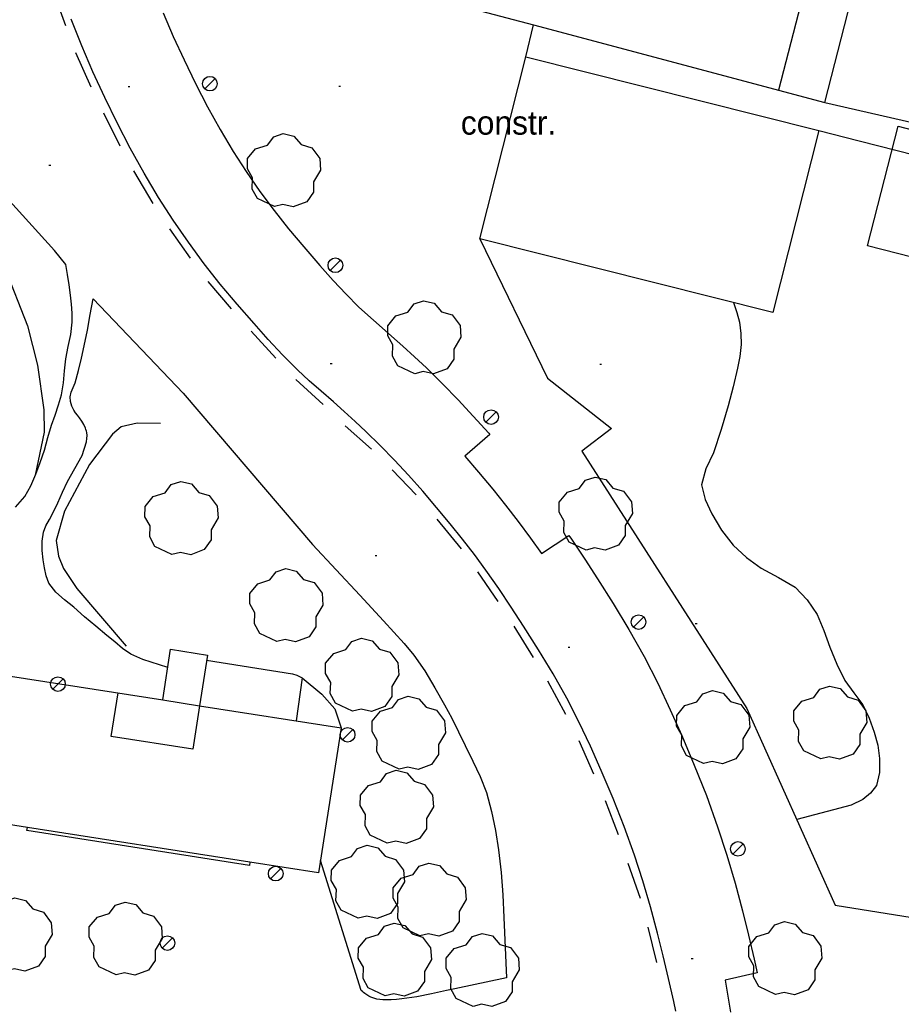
# Model space of a CAD drawing. Extents: x 431390 to 432653, y 4586754 to 4589600.
# Drawn here: x 431476.3 to 431524.5, y 4587127.2 to 4587181.2 of the extents above; entities that cross this region are included whole.
import ezdxf

# ---------------------------------------------------------------- set-up
doc = ezdxf.new("R2010")
doc.units = 0
for name, color, linetype in [('COM_06_LN', 7, 'Continuous'), ('COM_16_LN', 7, 'Continuous'), ('COM_17LS_LN', 7, 'Continuous'), ('CON_01_LN', 7, 'Continuous'), ('CON_01FI_LN', 7, 'Continuous'), ('CON_04_LN', 7, 'Continuous'), ('CON_06_LN', 7, 'Continuous'), ('CON_07_LN', 7, 'Continuous'), ('CON_15_LN', 7, 'Continuous'), ('CON_16_LN', 7, 'Continuous'), ('CON_19_LN', 7, 'Continuous'), ('ENE_06_PT', 7, 'Continuous'), ('ORO_03_PT', 7, 'Continuous'), ('TOP_13CN_TX', 7, 'Continuous'), ('VEG_03_PT', 7, 'Continuous'), ('VEG_04_LN', 7, 'Continuous'), ('VEG_07LS_LN', 7, 'Continuous')]:
    doc.layers.add(name, color=color, linetype=linetype)

msp = doc.modelspace()

# ---------------------------------------------------------------- linework, layer by layer
at = {"layer": 'COM_06_LN'}
msp.add_lwpolyline([(431515.31, 4587165.747), (431515.484, 4587165.212), (431515.63, 4587164.67), (431515.714, 4587164.062), (431515.73, 4587163.45), (431515.655, 4587162.808), (431515.53, 4587162.17), (431515.291, 4587161.135), (431515.01, 4587160.11), (431514.63, 4587158.819), (431514.21, 4587157.54), (431513.805, 4587156.659), (431513.56, 4587155.78), (431513.756, 4587154.98), (431514.13, 4587154.2), (431514.651, 4587153.304), (431515.29, 4587152.49), (431516.017, 4587151.813), (431516.82, 4587151.22), (431517.77, 4587150.725), (431518.68, 4587150.19), (431519.339, 4587149.497), (431519.88, 4587148.7), (431520.256, 4587147.821), (431520.58, 4587146.91), (431520.959, 4587145.978), (431521.4, 4587145.08), (431521.894, 4587144.417), (431522.38, 4587143.75), (431522.73, 4587143.028), (431523, 4587142.27), (431523.191, 4587141.551), (431523.29, 4587140.82), (431523.296, 4587140.057), (431523.12, 4587139.35), (431522.792, 4587138.928), (431522.37, 4587138.58), (431521.745, 4587138.272), (431518.764, 4587137.478)], dxfattribs=at)
at = {"layer": 'COM_16_LN'}
for points in [[(431478.81, 4587180.89), (431478.14, 4587182.76)], [(431480.2, 4587177.52), (431479.37, 4587179.41)], [(431481.79, 4587174.31), (431480.9, 4587176.11)], [(431483.59, 4587171.16), (431482.53, 4587172.96)], [(431485.63, 4587168.17), (431484.5, 4587169.78)], [(431487.87, 4587165.4), (431486.6, 4587166.9)], [(431490.29, 4587162.71), (431488.94, 4587164.18)], [(431492.89, 4587160.17), (431491.38, 4587161.55)], [(431495.52, 4587157.73), (431494.09, 4587159.01)], [(431497.96, 4587155.23), (431496.66, 4587156.61)], [(431500.44, 4587152.29), (431499.12, 4587153.91)], [(431502.44, 4587149.4), (431501.34, 4587151.03)], [(431504.38, 4587146.35), (431503.33, 4587148.06)], [(431506.15, 4587143.22), (431505.17, 4587145.05)], [(431507.68, 4587139.97), (431506.88, 4587141.78)], [(431509.02, 4587136.64), (431508.31, 4587138.51)], [(431510.22, 4587133.16), (431509.55, 4587135.09)], [(431511.12, 4587129.67), (431510.65, 4587131.6)]]:
    msp.add_lwpolyline(points, dxfattribs=at)
at = {"layer": 'COM_17LS_LN'}
for points in [[(431484.133, 4587181.599), (431484.685, 4587180.303), (431485.276, 4587179.015), (431485.905, 4587177.735), (431486.568, 4587176.459), (431487.255, 4587175.219), (431487.971, 4587174.018), (431488.679, 4587172.917), (431489.425, 4587171.832), (431490.199, 4587170.78), (431490.981, 4587169.789), (431491.817, 4587168.795), (431492.707, 4587167.779), (431493.435, 4587166.963), (431494.134, 4587166.204), (431494.804, 4587165.525), (431495.317, 4587165.054), (431495.936, 4587164.515), (431496.621, 4587163.915), (431497.242, 4587163.359), (431497.872, 4587162.791), (431498.532, 4587162.175), (431499.413, 4587161.307), (431500.261, 4587160.431), (431501.083, 4587159.548), (431501.929, 4587158.606), (431501.993, 4587158.531), (431500.633, 4587157.351), (431501.377, 4587156.486), (431502.157, 4587155.543), (431502.854, 4587154.674), (431503.54, 4587153.786), (431504.215, 4587152.873), (431504.81, 4587152.022), (431506.307, 4587153.022), (431506.448, 4587152.821), (431507.18, 4587151.723), (431507.874, 4587150.645), (431508.729, 4587149.297), (431509.591, 4587147.88), (431510.43, 4587146.391), (431511.175, 4587144.932), (431511.851, 4587143.492), (431512.482, 4587142.073), (431513.168, 4587140.459), (431513.827, 4587138.797), (431514.442, 4587137.093), (431514.945, 4587135.538), (431515.393, 4587134.003), (431515.804, 4587132.486), (431516.137, 4587131.169), (431516.445, 4587129.853), (431516.61, 4587129.105), (431514.854, 4587128.71), (431514.998, 4587127.831), (431515.143, 4587126.952)], [(431512.166, 4587127.005), (431512.04, 4587127.54), (431511.765, 4587128.788), (431511.473, 4587130.032), (431511.16, 4587131.27), (431510.772, 4587132.703), (431510.356, 4587134.128), (431509.9, 4587135.54), (431509.338, 4587137.096), (431508.727, 4587138.636), (431508.08, 4587140.16), (431507.486, 4587141.496), (431506.864, 4587142.819), (431506.2, 4587144.12), (431505.448, 4587145.454), (431504.651, 4587146.765), (431503.83, 4587148.06), (431503.165, 4587149.092), (431502.484, 4587150.114), (431501.78, 4587151.12), (431501.147, 4587151.976), (431500.495, 4587152.819), (431499.83, 4587153.65), (431499.084, 4587154.551), (431498.321, 4587155.439), (431497.54, 4587156.31), (431496.78, 4587157.126), (431496.004, 4587157.928), (431495.21, 4587158.71), (431494.627, 4587159.254), (431494.035, 4587159.788), (431493.44, 4587160.32), (431492.779, 4587160.899), (431492.116, 4587161.476), (431491.47, 4587162.07), (431490.66, 4587162.89), (431489.878, 4587163.739), (431489.11, 4587164.6), (431488.174, 4587165.669), (431487.26, 4587166.756), (431486.38, 4587167.87), (431485.513, 4587169.05), (431484.682, 4587170.258), (431483.89, 4587171.49), (431483.093, 4587172.826), (431482.338, 4587174.189), (431481.62, 4587175.57), (431480.94, 4587176.956), (431480.295, 4587178.36), (431479.69, 4587179.78), (431479.111, 4587181.254)], [(431525.92, 4587168.011), (431522.638, 4587168.852), (431524.313, 4587175.389), (431527.598, 4587174.547)]]:
    msp.add_lwpolyline(points, dxfattribs=at)
at = {"layer": 'CON_01_LN'}
msp.add_lwpolyline([(431493.124, 4587188.755), (431493.14, 4587188.711), (431493.706, 4587187.505), (431495.71, 4587183.235), (431504.385, 4587180.928)], dxfattribs=at)
at = {"layer": 'CON_01FI_LN'}
for points in [[(431520.299, 4587176.697), (431523, 4587187.223), (431523.952, 4587190.935), (431501.15, 4587196.755), (431498.849, 4587187.456), (431498.747, 4587187.043), (431498.539, 4587187.09), (431497.301, 4587187.471), (431493.124, 4587188.755)], [(431504.385, 4587180.928), (431520.299, 4587176.697)], [(431484.113, 4587144.024), (431484.545, 4587146.793), (431486.557, 4587146.479), (431486.124, 4587143.71), (431493.872, 4587142.5), (431492.633, 4587134.571), (431488.881, 4587135.157)], [(431476.715, 4587137.058), (431472.661, 4587137.691), (431473.9, 4587145.62), (431484.113, 4587144.024)], [(431488.881, 4587135.157), (431488.853, 4587134.978), (431476.687, 4587136.878), (431476.715, 4587137.058)]]:
    msp.add_lwpolyline(points, dxfattribs=at)
at = {"layer": 'CON_04_LN'}
for points in [[(431521.425, 4587191.58), (431520.314, 4587187.249), (431517.778, 4587177.367)], [(431484.113, 4587144.024), (431486.124, 4587143.71), (431485.753, 4587141.335), (431481.297, 4587142.031), (431481.668, 4587144.406)], [(431488.881, 4587135.157), (431476.715, 4587137.058)]]:
    msp.add_lwpolyline(points, dxfattribs=at)
at = {"layer": 'CON_06_LN'}
msp.add_lwpolyline([(431503.957, 4587179.188), (431519.965, 4587175.151), (431517.457, 4587165.206), (431501.449, 4587169.243), (431503.957, 4587179.188)], dxfattribs=at)
at = {"layer": 'CON_07_LN'}
msp.add_lwpolyline([(431486.512, 4587146.191), (431491.21, 4587145.46), (431491.44, 4587145.37), (431491.73, 4587145.24), (431491.402, 4587142.886)], dxfattribs=at)
at = {"layer": 'CON_15_LN'}
msp.add_lwpolyline([(431501.449, 4587169.243), (431505.138, 4587161.618), (431508.644, 4587158.874), (431507.022, 4587157.621), (431516.036, 4587143.553), (431520.864, 4587132.801), (431526.443, 4587131.905), (431525.002, 4587127.695)], dxfattribs=at)
at = {"layer": 'CON_16_LN'}
for points in [[(431519.965, 4587175.151), (431522.185, 4587174.591)], [(431491.73, 4587145.24), (431492.8, 4587144.34), (431493.52, 4587143.53), (431493.872, 4587142.5)]]:
    msp.add_lwpolyline(points, dxfattribs=at)
at = {"layer": 'CON_19_LN'}
for points in [[(431503.957, 4587179.188), (431504.385, 4587180.928)], [(431520.299, 4587176.697), (431527.717, 4587175.001)], [(431522.185, 4587174.591), (431527.269, 4587173.3)]]:
    msp.add_lwpolyline(points, dxfattribs=at)
at = {"layer": 'ENE_06_PT'}
for p, q in [((431486.972, 4587178.002), (431486.406, 4587177.436)), ((431493.832, 4587168.072), (431493.266, 4587167.506)), ((431502.342, 4587159.772), (431501.776, 4587159.206)), ((431510.402, 4587148.562), (431509.836, 4587147.996)), ((431478.667, 4587145.173), (431478.101, 4587144.607)), ((431494.502, 4587142.402), (431493.936, 4587141.836)), ((431515.832, 4587136.162), (431515.266, 4587135.596)), ((431490.572, 4587134.812), (431490.006, 4587134.246)), ((431484.652, 4587131.012), (431484.086, 4587130.446))]:
    msp.add_line(p, q, dxfattribs=at)
for centre in [(431486.689, 4587177.719), (431493.549, 4587167.789), (431502.059, 4587159.489), (431510.119, 4587148.279), (431478.384, 4587144.89), (431494.219, 4587142.119), (431515.549, 4587135.879), (431490.289, 4587134.529), (431484.369, 4587130.729)]:
    msp.add_circle(centre, 0.4, dxfattribs=at)
at = {"layer": 'ORO_03_PT'}
for p, q in [((431482.22, 4587177.56), (431482.32, 4587177.56)), ((431493.73, 4587177.58), (431493.83, 4587177.58)), ((431477.89, 4587173.27), (431477.99, 4587173.27)), ((431493.271, 4587162.416), (431493.371, 4587162.416)), ((431508, 4587162.38), (431508.1, 4587162.38)), ((431495.72, 4587151.93), (431495.82, 4587151.93)), ((431513.22, 4587148.21), (431513.32, 4587148.21)), ((431506.266, 4587146.913), (431506.366, 4587146.913)), ((431513, 4587129.878), (431513.1, 4587129.878))]:
    msp.add_line(p, q, dxfattribs=at)
at = {"layer": 'VEG_03_PT'}
for points in [[(431490.214, 4587171.001), (431489.287, 4587171.436), (431488.999, 4587171.957), (431489.022, 4587172.571), (431488.74, 4587173.063), (431488.748, 4587173.626), (431489.189, 4587174.161), (431489.842, 4587174.365), (431490.177, 4587174.816), (431490.703, 4587174.986), (431491.283, 4587174.853), (431491.683, 4587174.387), (431492.257, 4587174.217), (431492.691, 4587173.634), (431492.74, 4587172.992), (431492.357, 4587172.345), (431492.357, 4587171.795), (431491.985, 4587171.261), (431491.246, 4587170.986), (431490.681, 4587171.114), (431490.214, 4587171.001)], [(431497.884, 4587161.861), (431496.957, 4587162.296), (431496.669, 4587162.817), (431496.692, 4587163.431), (431496.41, 4587163.923), (431496.418, 4587164.486), (431496.859, 4587165.021), (431497.512, 4587165.225), (431497.847, 4587165.676), (431498.373, 4587165.846), (431498.953, 4587165.713), (431499.353, 4587165.247), (431499.927, 4587165.077), (431500.361, 4587164.494), (431500.41, 4587163.852), (431500.027, 4587163.205), (431500.027, 4587162.655), (431499.655, 4587162.121), (431498.916, 4587161.846), (431498.351, 4587161.974), (431497.884, 4587161.861)], [(431507.254, 4587152.221), (431506.327, 4587152.656), (431506.039, 4587153.177), (431506.062, 4587153.791), (431505.78, 4587154.283), (431505.788, 4587154.846), (431506.229, 4587155.381), (431506.882, 4587155.585), (431507.217, 4587156.036), (431507.743, 4587156.206), (431508.323, 4587156.073), (431508.723, 4587155.607), (431509.297, 4587155.437), (431509.731, 4587154.854), (431509.78, 4587154.212), (431509.397, 4587153.565), (431509.397, 4587153.015), (431509.025, 4587152.481), (431508.286, 4587152.206), (431507.721, 4587152.334), (431507.254, 4587152.221)], [(431484.614, 4587151.981), (431483.687, 4587152.416), (431483.399, 4587152.937), (431483.422, 4587153.551), (431483.14, 4587154.043), (431483.148, 4587154.606), (431483.589, 4587155.141), (431484.242, 4587155.345), (431484.577, 4587155.796), (431485.103, 4587155.966), (431485.683, 4587155.833), (431486.083, 4587155.367), (431486.657, 4587155.197), (431487.091, 4587154.614), (431487.14, 4587153.972), (431486.757, 4587153.325), (431486.757, 4587152.775), (431486.385, 4587152.241), (431485.646, 4587151.966), (431485.081, 4587152.094), (431484.614, 4587151.981)], [(431490.344, 4587147.221), (431489.417, 4587147.656), (431489.129, 4587148.177), (431489.152, 4587148.791), (431488.87, 4587149.283), (431488.878, 4587149.846), (431489.319, 4587150.381), (431489.972, 4587150.585), (431490.307, 4587151.036), (431490.833, 4587151.206), (431491.413, 4587151.073), (431491.813, 4587150.607), (431492.387, 4587150.437), (431492.821, 4587149.854), (431492.87, 4587149.212), (431492.487, 4587148.565), (431492.487, 4587148.015), (431492.115, 4587147.481), (431491.376, 4587147.206), (431490.811, 4587147.334), (431490.344, 4587147.221)], [(431494.484, 4587143.411), (431493.557, 4587143.846), (431493.269, 4587144.367), (431493.292, 4587144.981), (431493.01, 4587145.473), (431493.018, 4587146.036), (431493.459, 4587146.571), (431494.112, 4587146.775), (431494.447, 4587147.226), (431494.973, 4587147.396), (431495.553, 4587147.263), (431495.953, 4587146.797), (431496.527, 4587146.627), (431496.961, 4587146.044), (431497.01, 4587145.402), (431496.627, 4587144.755), (431496.627, 4587144.205), (431496.255, 4587143.671), (431495.516, 4587143.396), (431494.951, 4587143.524), (431494.484, 4587143.411)], [(431513.674, 4587140.551), (431512.747, 4587140.986), (431512.459, 4587141.507), (431512.482, 4587142.121), (431512.2, 4587142.613), (431512.208, 4587143.176), (431512.649, 4587143.711), (431513.302, 4587143.915), (431513.637, 4587144.366), (431514.163, 4587144.536), (431514.743, 4587144.403), (431515.143, 4587143.937), (431515.717, 4587143.767), (431516.151, 4587143.184), (431516.2, 4587142.542), (431515.817, 4587141.895), (431515.817, 4587141.345), (431515.445, 4587140.811), (431514.706, 4587140.536), (431514.141, 4587140.664), (431513.674, 4587140.551)], [(431520.074, 4587140.801), (431519.147, 4587141.236), (431518.859, 4587141.757), (431518.882, 4587142.371), (431518.6, 4587142.863), (431518.608, 4587143.426), (431519.049, 4587143.961), (431519.702, 4587144.165), (431520.037, 4587144.616), (431520.563, 4587144.786), (431521.143, 4587144.653), (431521.543, 4587144.187), (431522.117, 4587144.017), (431522.551, 4587143.434), (431522.6, 4587142.792), (431522.217, 4587142.145), (431522.217, 4587141.595), (431521.845, 4587141.061), (431521.106, 4587140.786), (431520.541, 4587140.914), (431520.074, 4587140.801)], [(431497.034, 4587140.241), (431496.107, 4587140.676), (431495.819, 4587141.197), (431495.842, 4587141.811), (431495.56, 4587142.303), (431495.568, 4587142.866), (431496.009, 4587143.401), (431496.662, 4587143.605), (431496.997, 4587144.056), (431497.523, 4587144.226), (431498.103, 4587144.093), (431498.503, 4587143.627), (431499.077, 4587143.457), (431499.511, 4587142.874), (431499.56, 4587142.232), (431499.177, 4587141.585), (431499.177, 4587141.035), (431498.805, 4587140.501), (431498.066, 4587140.226), (431497.501, 4587140.354), (431497.034, 4587140.241)], [(431496.384, 4587136.191), (431495.457, 4587136.626), (431495.169, 4587137.147), (431495.192, 4587137.761), (431494.91, 4587138.253), (431494.918, 4587138.816), (431495.359, 4587139.351), (431496.012, 4587139.555), (431496.347, 4587140.006), (431496.873, 4587140.176), (431497.453, 4587140.043), (431497.853, 4587139.577), (431498.427, 4587139.407), (431498.861, 4587138.824), (431498.91, 4587138.182), (431498.527, 4587137.535), (431498.527, 4587136.985), (431498.155, 4587136.451), (431497.416, 4587136.176), (431496.851, 4587136.304), (431496.384, 4587136.191)], [(431494.794, 4587132.091), (431493.867, 4587132.526), (431493.579, 4587133.047), (431493.602, 4587133.661), (431493.32, 4587134.153), (431493.328, 4587134.716), (431493.769, 4587135.251), (431494.422, 4587135.455), (431494.757, 4587135.906), (431495.283, 4587136.076), (431495.863, 4587135.943), (431496.263, 4587135.477), (431496.837, 4587135.307), (431497.271, 4587134.724), (431497.32, 4587134.082), (431496.937, 4587133.435), (431496.937, 4587132.885), (431496.565, 4587132.351), (431495.826, 4587132.076), (431495.261, 4587132.204), (431494.794, 4587132.091)], [(431498.174, 4587131.121), (431497.247, 4587131.556), (431496.959, 4587132.077), (431496.982, 4587132.691), (431496.7, 4587133.183), (431496.708, 4587133.746), (431497.149, 4587134.281), (431497.802, 4587134.485), (431498.137, 4587134.936), (431498.663, 4587135.106), (431499.243, 4587134.973), (431499.643, 4587134.507), (431500.217, 4587134.337), (431500.651, 4587133.754), (431500.7, 4587133.112), (431500.317, 4587132.465), (431500.317, 4587131.915), (431499.945, 4587131.381), (431499.206, 4587131.106), (431498.641, 4587131.234), (431498.174, 4587131.121)], [(431475.544, 4587129.211), (431474.617, 4587129.646), (431474.329, 4587130.167), (431474.352, 4587130.781), (431474.07, 4587131.273), (431474.078, 4587131.836), (431474.519, 4587132.371), (431475.172, 4587132.575), (431475.507, 4587133.026), (431476.033, 4587133.196), (431476.613, 4587133.063), (431477.013, 4587132.597), (431477.587, 4587132.427), (431478.021, 4587131.844), (431478.07, 4587131.202), (431477.687, 4587130.555), (431477.687, 4587130.005), (431477.315, 4587129.471), (431476.576, 4587129.196), (431476.011, 4587129.324), (431475.544, 4587129.211)], [(431481.564, 4587128.991), (431480.637, 4587129.426), (431480.349, 4587129.947), (431480.372, 4587130.561), (431480.09, 4587131.053), (431480.098, 4587131.616), (431480.539, 4587132.151), (431481.192, 4587132.355), (431481.527, 4587132.806), (431482.053, 4587132.976), (431482.633, 4587132.843), (431483.033, 4587132.377), (431483.607, 4587132.207), (431484.041, 4587131.624), (431484.09, 4587130.982), (431483.707, 4587130.335), (431483.707, 4587129.785), (431483.335, 4587129.251), (431482.596, 4587128.976), (431482.031, 4587129.104), (431481.564, 4587128.991)], [(431517.614, 4587127.921), (431516.687, 4587128.356), (431516.399, 4587128.877), (431516.422, 4587129.491), (431516.14, 4587129.983), (431516.148, 4587130.546), (431516.589, 4587131.081), (431517.242, 4587131.285), (431517.577, 4587131.736), (431518.103, 4587131.906), (431518.683, 4587131.773), (431519.083, 4587131.307), (431519.657, 4587131.137), (431520.091, 4587130.554), (431520.14, 4587129.912), (431519.757, 4587129.265), (431519.757, 4587128.715), (431519.385, 4587128.181), (431518.646, 4587127.906), (431518.081, 4587128.034), (431517.614, 4587127.921)], [(431496.274, 4587127.841), (431495.347, 4587128.276), (431495.059, 4587128.797), (431495.082, 4587129.411), (431494.8, 4587129.903), (431494.808, 4587130.466), (431495.249, 4587131.001), (431495.902, 4587131.205), (431496.237, 4587131.656), (431496.763, 4587131.826), (431497.343, 4587131.693), (431497.743, 4587131.227), (431498.317, 4587131.057), (431498.751, 4587130.474), (431498.8, 4587129.832), (431498.417, 4587129.185), (431498.417, 4587128.635), (431498.045, 4587128.101), (431497.306, 4587127.826), (431496.741, 4587127.954), (431496.274, 4587127.841)], [(431501.074, 4587127.271), (431500.147, 4587127.706), (431499.859, 4587128.227), (431499.882, 4587128.841), (431499.6, 4587129.333), (431499.608, 4587129.896), (431500.049, 4587130.431), (431500.702, 4587130.635), (431501.037, 4587131.086), (431501.563, 4587131.256), (431502.143, 4587131.123), (431502.543, 4587130.657), (431503.117, 4587130.487), (431503.551, 4587129.904), (431503.6, 4587129.262), (431503.217, 4587128.615), (431503.217, 4587128.065), (431502.845, 4587127.531), (431502.106, 4587127.256), (431501.541, 4587127.384), (431501.074, 4587127.271)]]:
    msp.add_lwpolyline(points, dxfattribs=at)
at = {"layer": 'VEG_04_LN'}
for points in [[(431473.45, 4587171.59), (431475.46, 4587167.68), (431476.72, 4587164.47), (431477.26, 4587162.32), (431477.62, 4587159.89), (431477.64, 4587158.67), (431477.14, 4587156.31)], [(431483.99, 4587159.13), (431482.71, 4587159.15), (431481.84, 4587158.95), (431481.37, 4587158.55), (431480.11, 4587156.89), (431478.75, 4587154.34), (431478.29, 4587152.74), (431478.42, 4587151.89), (431478.68, 4587151.21), (431479.42, 4587150.11), (431482.12, 4587146.97)]]:
    msp.add_lwpolyline(points, dxfattribs=at)
at = {"layer": 'VEG_07LS_LN'}
for points in [[(431476.063, 4587154.556), (431476.57, 4587155.15), (431476.905, 4587155.733), (431477.177, 4587156.361), (431477.42, 4587157), (431477.646, 4587157.676), (431477.84, 4587158.364), (431478.04, 4587159.05), (431478.229, 4587159.601), (431478.422, 4587160.152), (431478.58, 4587160.71), (431478.682, 4587161.361), (431478.74, 4587162.021), (431478.81, 4587162.68), (431478.941, 4587163.347), (431479.087, 4587164.012), (431479.17, 4587164.68), (431479.167, 4587165.173), (431479.131, 4587165.667), (431479.08, 4587166.16), (431479.003, 4587166.721), (431478.907, 4587167.281), (431478.81, 4587167.84), (431478.2, 4587168.59), (431474.34, 4587172.85)], [(431484.39, 4587145.802), (431483.016, 4587146.238), (431482.37, 4587146.53), (431481.916, 4587146.839), (431481.486, 4587147.192), (431481.06, 4587147.55), (431480.447, 4587148.052), (431479.842, 4587148.564), (431479.25, 4587149.09), (431478.751, 4587149.501), (431478.261, 4587149.921), (431477.89, 4587150.41), (431477.737, 4587150.813), (431477.642, 4587151.25), (431477.58, 4587151.69), (431477.527, 4587152.193), (431477.517, 4587152.702), (431477.59, 4587153.19), (431477.731, 4587153.544), (431477.922, 4587153.886), (431478.11, 4587154.23), (431478.378, 4587154.804), (431478.638, 4587155.383), (431478.9, 4587155.96), (431479.301, 4587156.674), (431479.707, 4587157.385), (431479.94, 4587158.14), (431479.96, 4587158.31), (431479.973, 4587158.482), (431479.96, 4587158.65), (431479.941, 4587158.728), (431479.917, 4587158.804), (431479.89, 4587158.88), (431479.801, 4587159.078), (431479.69, 4587159.268), (431479.57, 4587159.45), (431479.462, 4587159.587), (431479.348, 4587159.719), (431479.25, 4587159.86), (431479.143, 4587160.095), (431479.072, 4587160.349), (431479.05, 4587160.6), (431479.105, 4587160.858), (431479.215, 4587161.113), (431479.32, 4587161.37), (431479.511, 4587162.037), (431479.671, 4587162.712), (431479.82, 4587163.39), (431479.992, 4587164.24), (431480.147, 4587165.094), (431480.302, 4587165.948), (431485.23, 4587160.79), (431492.29, 4587152.53), (431493.591, 4587151.137), (431494.892, 4587149.744), (431496.18, 4587148.34), (431496.747, 4587147.73), (431497.311, 4587147.118), (431497.84, 4587146.48), (431498.444, 4587145.607), (431498.99, 4587144.691), (431499.51, 4587143.76), (431499.905, 4587143.025), (431500.284, 4587142.28), (431500.65, 4587141.53), (431501.063, 4587140.685), (431501.461, 4587139.832), (431501.8, 4587138.96), (431502.089, 4587137.932), (431502.301, 4587136.879), (431502.47, 4587135.82), (431502.619, 4587134.596), (431502.71, 4587133.364), (431502.75, 4587132.13), (431502.905, 4587128.824), (431500.069, 4587128.23), (431499.62, 4587128.14), (431498.81, 4587127.963), (431497.998, 4587127.798), (431497.18, 4587127.68), (431496.89, 4587127.649), (431496.6, 4587127.624), (431496.31, 4587127.62), (431496.146, 4587127.628), (431495.981, 4587127.642), (431495.82, 4587127.67), (431495.708, 4587127.7), (431495.597, 4587127.737), (431495.49, 4587127.78), (431495.376, 4587127.835), (431495.265, 4587127.899), (431495.16, 4587127.97), (431495.092, 4587128.024), (431495.026, 4587128.082), (431494.96, 4587128.14), (431492.738, 4587135.243)]]:
    msp.add_lwpolyline(points, dxfattribs=at)

# ---------------------------------------------------------------- texts
at = {"layer": 'TOP_13CN_TX'}
msp.add_text('constr.', height=1.3, dxfattribs=at).set_placement((431500.405, 4587174.931))

doc.saveas('drawing.dxf')
